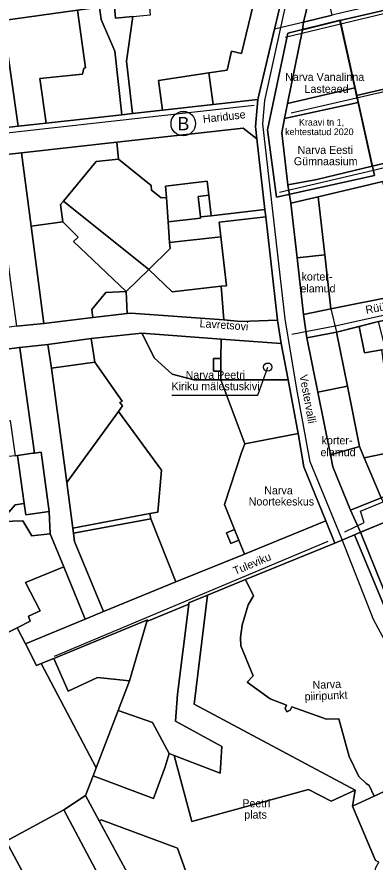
# Model space of a CAD drawing. Extents: x 728832 to 739469, y 6586263 to 6599699.
# Drawn here: x 738162 to 738430, y 6589449 to 6590082 of the extents above; entities that cross this region are included whole.
import ezdxf

# ---------------------------------------------------------------- set-up
doc = ezdxf.new("R2010")
doc.units = 0
for name, color, linetype in [('a_algatatud_dp', 7, 'Continuous'), ('a_piir', 7, 'Continuous'), ('v_dp_kehtiv', 7, 'Continuous'), ('v_dp_kehtiv_tekst', 7, 'Continuous'), ('v_dp_kontaktvoond', 7, 'Continuous'), ('v_dp_situatsioon_tekst', 7, 'Continuous'), ('v_dp_tanav_tekst', 7, 'Continuous'), ('v_dp_tekst', 7, 'Continuous'), ('v_dp_transp_bussipeatus', 7, 'Continuous'), ('v_olol_transp_jjt', 7, 'Continuous')]:
    doc.layers.add(name, color=color, linetype=linetype)

msp = doc.modelspace()

# ---------------------------------------------------------------- linework, layer by layer
at = {"layer": 'a_algatatud_dp'}
for points in [[(738401.48, 6589846.18), (738409.6, 6589805.84), (738418.68, 6589760.61), (738422.22, 6589752.2), (738434.8, 6589722.31), (738441.65, 6589708.72), (738519.97, 6589727.04), (738523.67, 6589727.04), (738523.67, 6589741.29), (738523.41, 6589778.3), (738520.95, 6589778.06), (738518.24, 6589794.66), (738518.26, 6589795.24), (738488.12, 6589792.92), (738487.06, 6589799.47), (738474.97, 6589861.7), (738432.98, 6589854.33)], [(738401.48, 6589846.18), (738418.36, 6589850.55), (738432.98, 6589854.33), (738474.97, 6589861.7), (738487.06, 6589799.47), (738488.12, 6589792.92), (738498.81, 6589793.75), (738518.26, 6589795.24), (738518.24, 6589794.66), (738520.95, 6589778.06), (738523.41, 6589778.3), (738523.67, 6589741.29), (738523.67, 6589727.04), (738519.97, 6589727.04), (738441.65, 6589708.72), (738434.8, 6589722.31), (738422.22, 6589752.2), (738418.68, 6589760.61), (738409.6, 6589805.84)]]:
    msp.add_lwpolyline(points, close=True, dxfattribs=at)
at = {"layer": 'a_piir'}
for points in [[(738126.92, 6590256.35), (738113.13, 6590254.89), (738122.17, 6590189.9), (738118.59, 6590189.44), (738124.38, 6590144.88), (738135.78, 6590057.17), (738141.69, 6590011.28), (738143.42, 6589998.35), (738162.79, 6590000.44), (738151.76, 6590079.67), (738148.59, 6590100.99), (738144.64, 6590129.01)], [(738229.2, 6590155.26), (738214.65, 6590153.96), (738216.77, 6590139.19), (738223.85, 6590089.7), (738225.18, 6590080.48), (738235.23, 6590056.78), (738240.59, 6590009.11), (738248.54, 6590010.01), (738244.14, 6590049.15), (738248.91, 6590082.61), (738235.84, 6590081.43)], [(738229.2, 6590155.26), (738235.84, 6590081.43), (738248.91, 6590082.61), (738262.11, 6590083.79), (738255.2, 6590157.59)], [(738144.64, 6590129.01), (738148.59, 6590100.99), (738151.76, 6590079.67), (738207.43, 6590087.42), (738223.85, 6590089.7), (738216.77, 6590139.19)], [(738386.7, 6590119.95), (738376.82, 6590078.35), (738398.11, 6590083.61), (738389.92, 6590119.18)], [(738493.5, 6590104.86), (738465.93, 6590098.46), (738458.25, 6590097.71), (738406.53, 6590085.7), (738398.11, 6590083.61), (738376.82, 6590078.35), (738376.03, 6590072.69), (738404.03, 6590079.58), (738494.45, 6590100.6)], [(738340.83, 6590098.65), (738330.23, 6590054.91), (738322.84, 6590056.7), (738319.39, 6590042.48), (738305.89, 6590040.45), (738309.1, 6590016.77), (738342.45, 6590020.49), (738360.01, 6590094.01)], [(738404.03, 6590079.58), (738415.18, 6590029.35), (738416.49, 6590023.5), (738506.94, 6590044.51), (738494.45, 6590100.6)], [(738207.43, 6590087.42), (738151.76, 6590079.67), (738162.79, 6590000.44), (738183.85, 6590002.79), (738179.09, 6590036.17), (738211.08, 6590039.58), (738211.99, 6590044.06), (738213.43, 6590044.22)], [(738223.85, 6590089.7), (738207.43, 6590087.42), (738213.43, 6590044.22), (738211.99, 6590044.06), (738211.08, 6590039.58), (738179.09, 6590036.17), (738183.85, 6590002.79), (738240.59, 6590009.11), (738235.23, 6590056.78), (738225.18, 6590080.48)], [(738364.71, 6590017.55), (738415.18, 6590029.35), (738404.03, 6590079.58), (738376.03, 6590072.69)], [(738738.99, 6590049.61), (738676.92, 6590033.37), (738666.76, 6590030.72), (738628.79, 6590020.79), (738620.33, 6590018.57), (738587.92, 6590010.1), (738570.92, 6590005.66), (738568.77, 6590005.09), (738537.68, 6589996.96), (738518.66, 6589991.84), (738428.26, 6589970.5), (738386.7, 6589960.54), (738364.99, 6589956.62), (738367.22, 6589942.76), (738387.74, 6589947.59), (738436.23, 6589958.98), (738466.5, 6589966.08), (738515.12, 6589977.52), (738553.84, 6589986.61), (738571.13, 6589991.27), (738600.07, 6589998.83), (738633.27, 6590007.58), (738689.52, 6590022.24), (738748.53, 6590037.67)], [(738305.89, 6590040.45), (738268.05, 6590034.77), (738271, 6590012.51), (738309.1, 6590016.77)], [(738416.49, 6590023.5), (738417.69, 6590018.13), (738428.26, 6589970.5), (738518.66, 6589991.84), (738506.94, 6590044.51)], [(738362.4, 6590006.18), (738417.69, 6590018.13), (738416.49, 6590023.5), (738415.18, 6590029.35), (738364.71, 6590017.55)], [(738342.45, 6590020.49), (738309.1, 6590016.77), (738271, 6590012.51), (738248.54, 6590010.01), (738240.59, 6590009.11), (738183.85, 6590002.79), (738162.79, 6590000.44), (738143.42, 6589998.35), (738075.76, 6589990.3), (738079.23, 6589969.61), (738112.06, 6589973.96), (738112.22, 6589972.59), (738130.34, 6589975.03), (738130.19, 6589976.37), (738130.16, 6589976.65), (738143.73, 6589978.63), (738143.79, 6589978.18), (738144.75, 6589978.3), (738165.3, 6589980.6), (738236.78, 6589988.57), (738331.46, 6589999.14), (738341.67, 6589991.02), (738340.62, 6590000.16)], [(738360.38, 6589995.57), (738364.99, 6589956.62), (738386.7, 6589960.54), (738428.26, 6589970.5), (738417.69, 6590018.13), (738362.4, 6590006.18)], [(738331.46, 6589999.14), (738236.78, 6589988.57), (738238.19, 6589975.88), (738262.45, 6589956.11), (738262.83, 6589952.64), (738269.99, 6589946.79), (738274, 6589947.07), (738273.41, 6589955.71), (738304.61, 6589959.35), (738305.77, 6589948.84), (738307.55, 6589933.5), (738347.74, 6589938.1), (738341.67, 6589991.02)], [(738236.78, 6589988.57), (738165.3, 6589980.6), (738172.52, 6589925.61), (738196.34, 6589928.89), (738194.67, 6589941.76), (738196.91, 6589944.37), (738221.36, 6589974), (738238.19, 6589975.88)], [(738165.3, 6589980.6), (738144.75, 6589978.3), (738149.84, 6589939.48), (738157.92, 6589877.99), (738161.73, 6589850.77), (738182.09, 6589852.78), (738172.52, 6589925.61)], [(738238.19, 6589975.88), (738221.36, 6589974), (738196.91, 6589944.37), (738260.8, 6589893.25), (738276.7, 6589908.87), (738276.35, 6589913.43), (738275.27, 6589928.98), (738274, 6589947.07), (738269.99, 6589946.79), (738262.83, 6589952.64), (738262.45, 6589956.11)], [(738304.61, 6589959.35), (738273.41, 6589955.71), (738274, 6589947.07), (738275.27, 6589928.98), (738299.52, 6589931.61), (738299.42, 6589932.62), (738297.76, 6589947.93), (738305.77, 6589948.84)], [(738436.23, 6589958.98), (738387.74, 6589947.59), (738392.67, 6589904.24), (738397.29, 6589863.7), (738447.46, 6589873.8), (738441.34, 6589903.92), (738444.47, 6589923.97), (738447.85, 6589924.67), (738446.68, 6589929.66), (738439.82, 6589928.84), (738439.21, 6589933.92), (738442.04, 6589934.25)], [(738297.76, 6589947.93), (738299.42, 6589932.62), (738307.55, 6589933.5), (738305.77, 6589948.84)], [(738387.74, 6589947.59), (738367.22, 6589942.76), (738371.87, 6589901.84), (738392.67, 6589904.24)], [(738196.91, 6589944.37), (738194.67, 6589941.76), (738196.34, 6589928.89), (738207.91, 6589917.52), (738204.42, 6589914.25), (738243.84, 6589876.79), (738260.8, 6589893.25)], [(738347.74, 6589938.1), (738307.55, 6589933.5), (738299.42, 6589932.62), (738299.52, 6589931.61), (738275.27, 6589928.98), (738276.35, 6589913.43), (738314.84, 6589917.56), (738313.6, 6589928.66), (738348.38, 6589932.61)], [(738348.38, 6589932.61), (738313.6, 6589928.66), (738314.84, 6589917.56), (738319.05, 6589881.03), (738315.13, 6589880.66), (738317.05, 6589855.47), (738329.51, 6589854.23), (738357.25, 6589855.33)], [(738196.34, 6589928.89), (738172.52, 6589925.61), (738182.09, 6589852.78), (738218.85, 6589857.16), (738218.13, 6589863.35), (738228.49, 6589876), (738243.84, 6589876.79), (738204.42, 6589914.25), (738207.91, 6589917.52)], [(738260.8, 6589893.25), (738278.41, 6589876.44), (738315.13, 6589880.66), (738319.05, 6589881.03), (738314.84, 6589917.56), (738276.35, 6589913.43), (738276.7, 6589908.87)], [(738371.87, 6589901.84), (738376.68, 6589859.56), (738397.29, 6589863.7), (738392.67, 6589904.24)], [(738260.8, 6589893.25), (738243.84, 6589876.79), (738244.6, 6589860.24), (738247.31, 6589860.56), (738317.05, 6589855.47), (738315.13, 6589880.66), (738278.41, 6589876.44)], [(738500.93, 6589884.54), (738483.22, 6589880.98), (738447.46, 6589873.8), (738397.29, 6589863.7), (738376.68, 6589859.56), (738379.29, 6589841.97), (738401.48, 6589846.18), (738418.36, 6589850.55), (738432.98, 6589854.33), (738504.33, 6589866.86), (738522.04, 6589867.21), (738523.04, 6589867.22), (738577.13, 6589865.85), (738565.45, 6589885.78), (738521.92, 6589885.14)], [(738243.84, 6589876.79), (738228.49, 6589876), (738218.13, 6589863.35), (738218.85, 6589857.16), (738244.6, 6589860.24)], [(738247.31, 6589860.56), (738244.6, 6589860.24), (738218.85, 6589857.16), (738182.09, 6589852.78), (738161.73, 6589850.77), (738134.58, 6589847.06), (738124.56, 6589845.69), (738096.21, 6589841.84), (738098.34, 6589825.95), (738130.93, 6589830.41), (738163.64, 6589834.73), (738164.05, 6589834.75), (738185.23, 6589837.11), (738217.68, 6589841.45), (738255.44, 6589845.42), (738314.96, 6589841.05), (738360.01, 6589837.72), (738357.25, 6589855.33), (738329.51, 6589854.23), (738317.05, 6589855.47)], [(738401.48, 6589846.18), (738409.6, 6589805.84), (738418.68, 6589760.61), (738422.22, 6589752.2), (738444, 6589756.69), (738436.88, 6589822.39), (738435.51, 6589833.15), (738422.32, 6589830.84), (738418.36, 6589850.55)], [(738432.98, 6589854.33), (738418.36, 6589850.55), (738422.32, 6589830.84), (738435.51, 6589833.15), (738438.28, 6589833.71)], [(738255.44, 6589845.42), (738217.68, 6589841.45), (738220.22, 6589823.74), (738240.7, 6589794.7), (738239.16, 6589793.62), (738241.02, 6589791), (738238, 6589786.86), (738270.38, 6589742.95), (738267.58, 6589711.56), (738261.68, 6589710.45), (738262.43, 6589706.5), (738281.11, 6589659.28), (738332.56, 6589679.96), (738328.28, 6589690.47), (738322.17, 6589687.99), (738318.9, 6589696.11), (738324.99, 6589698.56), (738317.54, 6589717.34), (738330.47, 6589756.98), (738332.68, 6589762.77), (738314.8, 6589810.59), (738294.49, 6589810.59), (738278.4, 6589814.94), (738264.94, 6589826.74)], [(738255.44, 6589845.42), (738264.94, 6589826.74), (738278.4, 6589814.94), (738294.49, 6589810.59), (738314.8, 6589810.59), (738314.83, 6589816.98), (738309.32, 6589816.96), (738309.29, 6589826.45), (738314.88, 6589826.47), (738314.96, 6589841.05)], [(738401.48, 6589846.18), (738379.29, 6589841.97), (738387.53, 6589801.37), (738409.6, 6589805.84)], [(738217.68, 6589841.45), (738185.23, 6589837.11), (738187.77, 6589819.4), (738220.22, 6589823.74)], [(738314.96, 6589841.05), (738314.88, 6589826.47), (738314.83, 6589816.98), (738314.8, 6589810.59), (738365.27, 6589810.6), (738360.01, 6589837.72)], [(738164.05, 6589834.75), (738163.64, 6589834.73), (738130.93, 6589830.41), (738130.91, 6589829.92), (738135.02, 6589794.79), (738132.67, 6589794.44), (738134.63, 6589780.25), (738134.51, 6589780.23), (738134.93, 6589776.76), (738156.89, 6589780.01), (738160.75, 6589753.72), (738162.5, 6589753.96), (738173.99, 6589755.56), (738175.09, 6589755.7), (738164.09, 6589834.39)], [(738185.23, 6589837.11), (738164.05, 6589834.75), (738164.09, 6589834.39), (738175.09, 6589755.7), (738180.07, 6589756.4), (738186.1, 6589711.93), (738186.94, 6589695.26), (738197.05, 6589670.52), (738213.06, 6589631.45), (738226.88, 6589637.01), (738205.15, 6589689.51), (738204.34, 6589695.71), (738203.83, 6589699.44), (738199.25, 6589733.67), (738187.77, 6589819.4)], [(738314.88, 6589826.47), (738309.29, 6589826.45), (738309.32, 6589816.96), (738314.83, 6589816.98)], [(738187.77, 6589819.4), (738199.25, 6589733.67), (738238, 6589786.86), (738241.02, 6589791), (738239.16, 6589793.62), (738240.7, 6589794.7), (738220.22, 6589823.74)], [(738365.27, 6589810.6), (738314.8, 6589810.59), (738332.68, 6589762.77), (738372.68, 6589770.46)], [(738387.53, 6589801.37), (738397, 6589754.36), (738418.68, 6589760.61), (738409.6, 6589805.84)], [(738238, 6589786.86), (738199.25, 6589733.67), (738203.83, 6589699.44), (738261.68, 6589710.45), (738267.58, 6589711.56), (738270.38, 6589742.95)], [(738330.47, 6589756.98), (738317.54, 6589717.34), (738324.99, 6589698.56), (738328.28, 6589690.47), (738332.56, 6589679.96), (738393.34, 6589704.92), (738376.88, 6589745.55), (738372.68, 6589770.46), (738332.68, 6589762.77)], [(738508.25, 6589769.95), (738466.92, 6589761.42), (738444, 6589756.69), (738422.22, 6589752.2), (738434.8, 6589722.31), (738442.27, 6589725.35), (738516.71, 6589740.73), (738511.55, 6589765.74)], [(738138.2, 6589753.65), (738138.81, 6589749.78), (738142.13, 6589726.98), (738143.97, 6589727.17), (738145.62, 6589712.75), (738149.92, 6589713.41), (738150.3, 6589710.77), (738155.93, 6589711.45), (738160.76, 6589717.06), (738167.5, 6589718.08), (738162.5, 6589753.96), (738160.75, 6589753.72), (738156, 6589753.06), (738154.37, 6589755.99)], [(738180.07, 6589756.4), (738175.09, 6589755.7), (738173.99, 6589755.56), (738162.5, 6589753.96), (738167.5, 6589718.08), (738168.67, 6589709.44), (738186.1, 6589711.93)], [(738398.78, 6589745.38), (738412.05, 6589712.99), (738434.8, 6589722.31), (738422.22, 6589752.2), (738418.68, 6589760.61), (738397, 6589754.36)], [(738167.5, 6589718.08), (738160.76, 6589717.06), (738155.93, 6589711.45), (738150.3, 6589710.77), (738149.92, 6589713.41), (738145.62, 6589712.75), (738135.94, 6589711.05), (738115.13, 6589700.41), (738115.97, 6589694.1), (738135.21, 6589703.93), (738166.41, 6589704.98), (738173.19, 6589693.8), (738186.94, 6589695.26), (738186.1, 6589711.93), (738168.67, 6589709.44)], [(738135.21, 6589703.93), (738115.97, 6589694.1), (738153.58, 6589620.53), (738162.14, 6589624.93), (738171.87, 6589629.91), (738170.55, 6589633.57), (738179.28, 6589637.49), (738168.44, 6589658.74), (738197.05, 6589670.52), (738186.94, 6589695.26), (738173.19, 6589693.8), (738166.41, 6589704.98)], [(738393.34, 6589704.92), (738332.56, 6589679.96), (738281.11, 6589659.28), (738226.88, 6589637.01), (738213.06, 6589631.45), (738168.27, 6589612.97), (738176.62, 6589596.65), (738180.22, 6589598.13), (738189.52, 6589601.95), (738259.7, 6589630.74), (738259.39, 6589629.69), (738290.78, 6589642.61), (738290.89, 6589643.54), (738304.84, 6589649.26), (738333.36, 6589660.95), (738400.07, 6589688.32)], [(738261.68, 6589710.45), (738203.83, 6589699.44), (738204.34, 6589695.71), (738262.43, 6589706.5)], [(738262.43, 6589706.5), (738204.34, 6589695.71), (738205.15, 6589689.51), (738226.88, 6589637.01), (738281.11, 6589659.28)], [(738451.79, 6589709.85), (738419.38, 6589696.58), (738436.27, 6589655.01), (738465.9, 6589667.04), (738455.85, 6589710.7)], [(738328.28, 6589690.47), (738324.99, 6589698.56), (738318.9, 6589696.11), (738322.17, 6589687.99)], [(738419.38, 6589696.58), (738414.93, 6589694.42), (738437.9, 6589639.26), (738498.5, 6589530.65), (738503.41, 6589532.61), (738497.26, 6589543.58), (738472.37, 6589588.12), (738458.4, 6589613.29), (738439.01, 6589648.26), (738436.27, 6589655.01)], [(738168.27, 6589612.97), (738213.06, 6589631.45), (738197.05, 6589670.52), (738168.44, 6589658.74), (738179.28, 6589637.49), (738170.55, 6589633.57), (738171.87, 6589629.91), (738162.14, 6589624.93)], [(738304.84, 6589649.26), (738294.85, 6589567.82), (738415.44, 6589503.33), (738413.41, 6589491.43), (738429.62, 6589498.93), (738426, 6589506.7), (738423.7, 6589508.19), (738418.07, 6589513.62), (738410.97, 6589528.53), (738403.1, 6589556.75), (738393.86, 6589556.45), (738367.86, 6589565.69), (738366.77, 6589563.19), (738364.15, 6589561.87), (738363.08, 6589564.61), (738364, 6589566.94), (738351.81, 6589571.67), (738334.47, 6589584.25), (738339.04, 6589588.91), (738329.85, 6589611.33), (738329.42, 6589617.57), (738330.79, 6589626.94), (738335.16, 6589642.21), (738339.18, 6589648.89), (738333.36, 6589660.95)], [(738304.84, 6589649.26), (738290.89, 6589643.54), (738290.78, 6589642.61), (738282.36, 6589575.25), (738280.9, 6589555), (738315.57, 6589535.92), (738314.26, 6589516.09), (738279.67, 6589529.29), (738293.14, 6589479.77), (738380.39, 6589503.71), (738397.41, 6589495.04), (738415.44, 6589503.33), (738294.85, 6589567.82)], [(738290.78, 6589642.61), (738259.39, 6589629.69), (738246.4, 6589585.22), (738237.76, 6589562.92), (738263.62, 6589553.9), (738276.05, 6589530.67), (738279.67, 6589529.29), (738314.26, 6589516.09), (738315.57, 6589535.92), (738280.9, 6589555), (738282.36, 6589575.25)], [(738259.39, 6589629.69), (738259.7, 6589630.74), (738189.52, 6589601.95), (738200.27, 6589577.35), (738222.26, 6589587.64), (738246.4, 6589585.22)], [(738162.14, 6589624.93), (738153.58, 6589620.53), (738128.09, 6589615.25), (738113.92, 6589577.33), (738102.74, 6589563.55), (738095.06, 6589526.95), (738105.07, 6589513.53), (738126.52, 6589484.82), (738153.81, 6589465.24), (738197.12, 6589488.59), (738213.31, 6589499.39), (738218.99, 6589514.16), (738221.3, 6589520.13), (738180.22, 6589598.13), (738176.62, 6589596.65), (738168.27, 6589612.97)], [(738189.52, 6589601.95), (738180.22, 6589598.13), (738221.3, 6589520.13), (738237.76, 6589562.92), (738246.4, 6589585.22), (738222.26, 6589587.64), (738200.27, 6589577.35)], [(738237.76, 6589562.92), (738221.3, 6589520.13), (738218.99, 6589514.16), (738264.37, 6589497.09), (738273.07, 6589520.88), (738276.05, 6589530.67), (738263.62, 6589553.9)], [(738276.05, 6589530.67), (738273.07, 6589520.88), (738264.37, 6589497.09), (738218.99, 6589514.16), (738213.31, 6589499.39), (738223.64, 6589480.33), (738225.13, 6589481.12), (738282.31, 6589459.96), (738305.05, 6589396.47), (738313.28, 6589399.33), (738339.92, 6589408.58), (738388.38, 6589425.39), (738417.71, 6589435.57), (738429.84, 6589439.77), (738430.85, 6589445.29), (738433.05, 6589449.51), (738430.63, 6589450.56), (738413.41, 6589491.43), (738415.44, 6589503.33), (738397.41, 6589495.04), (738380.39, 6589503.71), (738293.14, 6589479.77), (738279.67, 6589529.29)], [(738213.31, 6589499.39), (738197.12, 6589488.59), (738248.88, 6589391.21), (738253.85, 6589381.52), (738280.42, 6589331.88), (738292.59, 6589308.97), (738310.18, 6589275.92), (738316.48, 6589263.88), (738352.56, 6589197.3), (738381.1, 6589211.48), (738370.84, 6589239.88), (738362.24, 6589236.78), (738356.68, 6589234.77), (738223.64, 6589480.33)], [(738153.81, 6589465.24), (738169.71, 6589435.73), (738182.53, 6589442.55), (738218.4, 6589375.02), (738248.88, 6589391.21), (738197.12, 6589488.59)], [(738225.13, 6589481.12), (738223.64, 6589480.33), (738356.68, 6589234.77), (738362.24, 6589236.78), (738305.05, 6589396.47), (738282.31, 6589459.96)], [(738153.81, 6589465.24), (738087.22, 6589429.83), (738103.27, 6589399.44), (738133.59, 6589415.85), (738169.71, 6589435.73)]]:
    msp.add_lwpolyline(points, close=True, dxfattribs=at)
for points in [[(738360.01, 6590094.01), (738342.45, 6590020.49), (738340.62, 6590000.16), (738341.67, 6589991.02), (738347.74, 6589938.1), (738348.38, 6589932.61), (738357.25, 6589855.33), (738360.01, 6589837.72), (738365.27, 6589810.6), (738372.68, 6589770.46), (738376.88, 6589745.55), (738393.34, 6589704.92), (738400.07, 6589688.32), (738414.93, 6589694.42), (738419.38, 6589696.58), (738412.05, 6589712.99), (738398.78, 6589745.38), (738397, 6589754.36), (738387.53, 6589801.37), (738379.29, 6589841.97), (738376.68, 6589859.56), (738371.87, 6589901.84), (738367.22, 6589942.76), (738364.99, 6589956.62), (738360.38, 6589995.57), (738362.4, 6590006.18), (738364.71, 6590017.55), (738376.03, 6590072.69), (738376.82, 6590078.35), (738386.7, 6590119.95)], [(738248.91, 6590082.61), (738244.14, 6590049.15), (738248.54, 6590010.01), (738271, 6590012.51), (738268.05, 6590034.77), (738305.89, 6590040.45), (738319.39, 6590042.48), (738322.84, 6590056.7), (738330.23, 6590054.91), (738340.83, 6590098.65)], [(738434.8, 6589722.31), (738412.05, 6589712.99), (738419.38, 6589696.58), (738451.79, 6589709.85)], [(738437.9, 6589639.26), (738414.93, 6589694.42), (738400.07, 6589688.32), (738333.36, 6589660.95), (738339.18, 6589648.89), (738335.16, 6589642.21), (738330.79, 6589626.94), (738329.42, 6589617.57), (738329.85, 6589611.33), (738339.04, 6589588.91), (738334.47, 6589584.25), (738351.81, 6589571.67), (738364, 6589566.94), (738363.08, 6589564.61), (738364.15, 6589561.87), (738366.77, 6589563.19), (738367.86, 6589565.69), (738393.86, 6589556.45), (738403.1, 6589556.75), (738410.97, 6589528.53), (738418.07, 6589513.62), (738423.7, 6589508.19), (738426, 6589506.7), (738429.62, 6589498.93), (738451.12, 6589508.87)], [(738451.12, 6589508.87), (738429.62, 6589498.93), (738413.41, 6589491.43), (738430.63, 6589450.56)]]:
    msp.add_lwpolyline(points, dxfattribs=at)
at = {"layer": 'v_dp_kehtiv'}
for points in [[(738356.45, 6589947.4), (738429.89, 6589963.68), (738429.89, 6589963.68), (738404.16, 6590079.99), (738364.96, 6590070.28), (738349.68, 6589997.76), (738356.45, 6589947.4)], [(738356.45, 6589947.4), (738349.68, 6589997.76), (738364.96, 6590070.28), (738404.16, 6590079.99), (738429.89, 6589963.68)]]:
    msp.add_lwpolyline(points, close=True, dxfattribs=at)
msp.add_lwpolyline([(738447.46, 6589873.8), (738397.29, 6589863.7), (738401.48, 6589846.18), (738418.36, 6589850.55), (738432.98, 6589854.33)], dxfattribs=at)
msp.add_lwpolyline([(738447.46, 6589873.8), (738397.29, 6589863.7), (738401.48, 6589846.18), (738418.36, 6589850.55), (738432.98, 6589854.33)], dxfattribs=at)
at = {"layer": 'v_dp_kontaktvoond'}
msp.add_lwpolyline([(738451.79, 6589709.85), (738400.07, 6589688.32), (738393.34, 6589704.92), (738376.88, 6589745.55), (738372.68, 6589770.46), (738365.27, 6589810.6), (738360.01, 6589837.72), (738357.25, 6589855.33), (738348.38, 6589932.61), (738347.74, 6589938.1), (738341.67, 6589991.02), (738340.62, 6590000.16), (738342.45, 6590020.49), (738355.08, 6590073.37), (738355.08, 6590073.37), (738398.07, 6590083.62)], dxfattribs=at)
at = {"layer": 'v_dp_situatsioon_tekst'}
msp.add_lwpolyline([(738277.96, 6589799.15), (738342.49, 6589799.15), (738349.91, 6589820.1)], dxfattribs=at)
msp.add_circle((738349.91, 6589820.1), 3.08, dxfattribs=at)
at = {"layer": 'v_dp_transp_bussipeatus'}
msp.add_circle((738286.59, 6590002.43), 9.17, dxfattribs=at)
at = {"layer": 'v_olol_transp_jjt'}
msp.add_line((738362.91, 6590067.21), (738505.73, 6590101.28), dxfattribs=at)
for points in [[(738494.3, 6589522.89), (738489.28, 6589522.16), (738476.64, 6589543.02), (738429.23, 6589631.12), (738404.91, 6589692.73), (738381.65, 6589749.21), (738371.67, 6589803.51), (738362.9, 6589856.18), (738346.3, 6590002.27), (738347.8, 6590019.69), (738347.8, 6590019.69), (738347.8, 6590019.69), (738347.8, 6590019.69), (738363.94, 6590093.67)], [(738512.94, 6590040.89), (738510.02, 6590042.96), (738367.4, 6590010.35), (738367.4, 6590010.35)], [(738339.63, 6590015.89), (738339.63, 6590015.89), (738339.63, 6590015.89), (738076.06, 6589986.46)], [(738519.81, 6589990.12), (738429.09, 6589967.32), (738358.64, 6589950.98)], [(738367.95, 6589844.86), (738400.33, 6589850.98), (738494.23, 6589871.8), (738512.17, 6589872.81), (738567.1, 6589873.85)], [(738407.73, 6589696.77), (738422.16, 6589703.71), (738419.35, 6589712.26), (738437.74, 6589719.82), (738464.29, 6589726.37), (738517.92, 6589737.38), (738528.97, 6589737.38), (738600.32, 6589738.94), (738611.88, 6589738.94), (738645.28, 6589734.86), (738677.57, 6589729.69), (738705.8, 6589722.26), (738746.3, 6589710.17)], [(738190, 6589603.76), (738395.17, 6589689.8)]]:
    msp.add_lwpolyline(points, dxfattribs=at)

# ---------------------------------------------------------------- texts
at = {"layer": 'v_dp_kehtiv_tekst'}
for s, p in [('Kraavi tn 1,', (738373.29, 6590000.96)), ('kehtestatud 2020', (738362.96, 6589993.82))]:
    msp.add_text(s, height=5, dxfattribs=at).set_placement(p)
at = {"layer": 'v_dp_situatsioon_tekst'}
for s, p in [('Narva Vanalinna ', (738362.92, 6590034.36)), ('Lasteaed', (738377.47, 6590025.46)), ('Narva Eesti ', (738372.27, 6589979.75)), ('Gümnaasium', (738369.48, 6589971.27)), ('Narva Peetri ', (738288.38, 6589811.28)), ('Kiriku mälestuskivi', (738277.8, 6589802.8)), ('Narva ', (738347.28, 6589724.79)), ('Noortekeskus', (738335.62, 6589716.47)), ('Peetri', (738330.85, 6589490.5)), ('plats', (738332.33, 6589482.02))]:
    msp.add_text(s, height=6, dxfattribs=at).set_placement(p)
for s, p in [('Narva', (738383.59, 6589579.01)), ('piiripunkt', (738377.68, 6589570.42))]:
    msp.add_text(s, height=6, rotation=2.52068, dxfattribs=at).set_placement(p)
at = {"layer": 'v_dp_tanav_tekst'}
for s, rotation, p in [('Hariduse', 6.54556, (738301.65, 6590002.89)), ('Rüütli', 10.83306, (738423.83, 6589859.9)), ('Lavretsovi', 356.02676, (738298.69, 6589850.02)), ('Vestervalli', 280.35202, (738373.71, 6589813.86)), ('Tuleviku', 22.63032, (738325.48, 6589664.37))]:
    msp.add_text(s, height=6, rotation=rotation, dxfattribs=at).set_placement(p)
at = {"layer": 'v_dp_tekst'}
for s, p in [('korter-', (738375.22, 6589884.93)), ('elamud', (738374.41, 6589876.03)), ('korter-', (738390.26, 6589762.29)), ('elamud', (738389.44, 6589753.38))]:
    msp.add_text(s, height=6, dxfattribs=at).set_placement(p)
at = {"layer": 'v_dp_transp_bussipeatus'}
msp.add_text('B', height=10, dxfattribs=at).set_placement((738282.3, 6589997.43))

doc.saveas('drawing.dxf')
